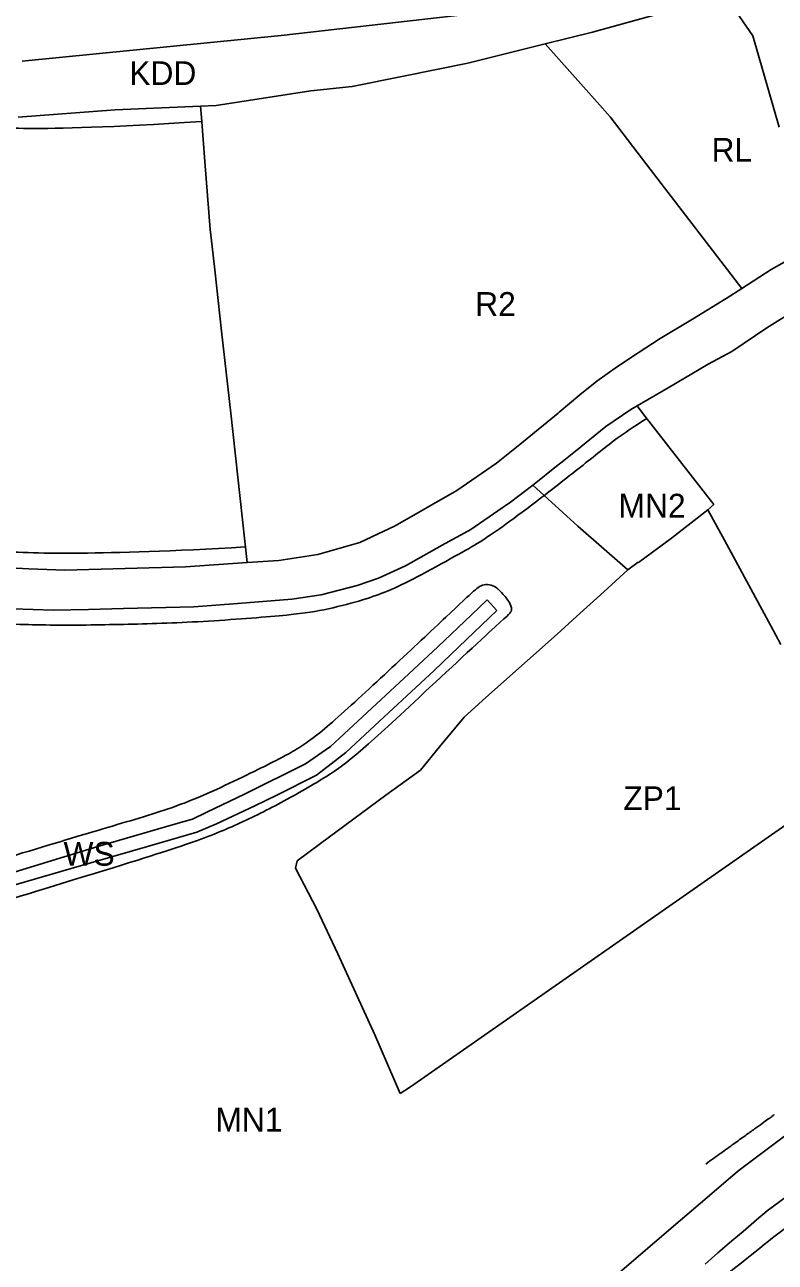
# Model space of a CAD drawing. Extents: x 7413438 to 7416393, y 5541665 to 5544118.
# Drawn here: x 7414642.6 to 7414832.1, y 5542969.5 to 5543282 of the extents above; entities that cross this region are included whole.
import ezdxf

# ---------------------------------------------------------------- set-up
doc = ezdxf.new("R2010")
doc.units = 0
for name, color, linetype in [('linie_rozgraniczajace', 7, 'Continuous'), ('linie_zabudowy_nieprzekraczalne', 7, 'Continuous'), ('oznaczenia_przeznaczen', 7, 'Continuous')]:
    doc.layers.add(name, color=color, linetype=linetype)

msp = doc.modelspace()

# ---------------------------------------------------------------- linework, layer by layer
at = {"layer": 'linie_rozgraniczajace'}
for p, q in [((7414785.95, 5543280.15), (7414819.64, 5543289.46)), ((7414765.82, 5543285.93), (7414707.33, 5543279.31)), ((7414826.4, 5543279.18), (7414820.45, 5543287.85)), ((7414774.02, 5543277.18), (7414785.95, 5543280.15)), ((7414707.33, 5543279.31), (7414641.96, 5543272.83)), ((7414754.51, 5543272.33), (7414774.02, 5543277.18)), ((7414774.02, 5543277.18), (7414787.16, 5543262.42)), ((7414833.08, 5543256.17), (7414826.4, 5543279.18)), ((7414738.24, 5543269.03), (7414754.51, 5543272.33)), ((7414725.25, 5543266.39), (7414738.24, 5543269.03)), ((7414690.96, 5543261.63), (7414714.83, 5543265.29)), ((7414714.83, 5543265.29), (7414725.25, 5543266.39)), ((7414665.43, 5543260.51), (7414686.96, 5543261.45)), ((7414686.96, 5543261.45), (7414690.96, 5543261.63)), ((7414686.96, 5543261.45), (7414687.19, 5543258.54)), ((7414787.16, 5543262.42), (7414790.41, 5543258.78)), ((7414640.94, 5543258.66), (7414665.43, 5543260.51)), ((7414687.19, 5543258.54), (7414688.08, 5543247.46)), ((7414790.41, 5543258.78), (7414800.54, 5543245.56)), ((7414688.08, 5543247.46), (7414689.46, 5543230.34)), ((7414800.54, 5543245.56), (7414823.62, 5543215.43)), ((7414689.46, 5543230.34), (7414689.94, 5543226.05)), ((7414689.94, 5543226.05), (7414690.6, 5543220.16)), ((7414831.03, 5543220.18), (7414837.77, 5543224.01)), ((7414690.6, 5543220.16), (7414692.29, 5543204.62)), ((7414823.62, 5543215.43), (7414831.03, 5543220.18)), ((7414819.69, 5543212.89), (7414823.62, 5543215.43)), ((7414811.22, 5543207.68), (7414819.69, 5543212.89)), ((7414803.07, 5543202.81), (7414811.22, 5543207.68)), ((7414829.99, 5543205.49), (7414838, 5543210.55)), ((7414692.29, 5543204.62), (7414694.63, 5543183.95)), ((7414821.13, 5543199.5), (7414829.99, 5543205.49)), ((7414797.5, 5543199.17), (7414803.07, 5543202.81)), ((7414792.25, 5543195.73), (7414797.5, 5543199.17)), ((7414815.11, 5543196.3), (7414821.13, 5543199.5)), ((7414787.07, 5543192.04), (7414792.25, 5543195.73)), ((7414805.07, 5543190.34), (7414815.11, 5543196.3)), ((7414782.74, 5543188.58), (7414787.07, 5543192.04)), ((7414797.21, 5543185.78), (7414805.07, 5543190.34)), ((7414777.52, 5543184.14), (7414782.74, 5543188.58)), ((7414795.59, 5543184.85), (7414797.21, 5543185.78)), ((7414797.21, 5543185.78), (7414798.67, 5543183.87)), ((7414694.63, 5543183.95), (7414698.76, 5543146.21)), ((7414767.58, 5543175.98), (7414777.26, 5543183.94)), ((7414777.26, 5543183.94), (7414777.52, 5543184.14)), ((7414789.32, 5543180.6), (7414795.59, 5543184.85)), ((7414798.67, 5543183.87), (7414798.72, 5543183.86)), ((7414798.72, 5543183.86), (7414798.69, 5543183.84)), ((7414798.69, 5543183.84), (7414816.59, 5543160.87)), ((7414781.66, 5543174.36), (7414789.32, 5543180.6)), ((7414761.68, 5543171.27), (7414767.58, 5543175.98)), ((7414779.09, 5543172.32), (7414781.66, 5543174.36)), ((7414751.68, 5543164.42), (7414761.68, 5543171.27)), ((7414771.19, 5543166.02), (7414776.85, 5543170.54)), ((7414776.85, 5543170.54), (7414777.94, 5543171.41)), ((7414777.94, 5543171.41), (7414779.09, 5543172.32)), ((7414736.12, 5543155.52), (7414751.68, 5543164.42)), ((7414765.23, 5543161.48), (7414770.89, 5543165.79)), ((7414770.89, 5543165.79), (7414771.19, 5543166.02)), ((7414782.27, 5543155.39), (7414770.89, 5543165.79)), ((7414763.89, 5543160.56), (7414765.23, 5543161.48)), ((7414816.59, 5543160.87), (7414815.1, 5543159.53)), ((7414755.22, 5543154.56), (7414763.17, 5543160.06)), ((7414763.17, 5543160.06), (7414763.89, 5543160.56)), ((7414815.1, 5543159.53), (7414805.87, 5543152.38)), ((7414815.1, 5543159.53), (7414819.25, 5543151.86)), ((7414730.26, 5543152.74), (7414736.12, 5543155.52)), ((7414747.98, 5543150.57), (7414755.22, 5543154.56)), ((7414794.9, 5543144.34), (7414782.27, 5543155.39)), ((7414727.18, 5543151.28), (7414730.26, 5543152.74)), ((7414805.87, 5543152.38), (7414797.54, 5543146.25)), ((7414819.25, 5543151.86), (7414830.96, 5543130.25)), ((7414706.73, 5543146.75), (7414716.63, 5543148.28)), ((7414716.63, 5543148.28), (7414727.18, 5543151.28)), ((7414738.72, 5543145.38), (7414747.98, 5543150.57)), ((7414643.66, 5543144.59), (7414633.27, 5543145.15)), ((7414683.2, 5543145.15), (7414652.69, 5543144.3)), ((7414698.76, 5543146.21), (7414683.2, 5543145.15)), ((7414698.76, 5543146.21), (7414706.73, 5543146.75)), ((7414731.88, 5543142.29), (7414738.72, 5543145.38)), ((7414797.49, 5543146.3), (7414794.9, 5543144.34)), ((7414797.54, 5543146.25), (7414797.49, 5543146.3)), ((7414652.69, 5543144.3), (7414643.66, 5543144.59)), ((7414726.55, 5543140.45), (7414731.88, 5543142.29)), ((7414788.82, 5543138.82), (7414794.9, 5543144.34)), ((7414717.47, 5543138.08), (7414726.55, 5543140.45)), ((7414685.32, 5543135.07), (7414696.39, 5543135.89)), ((7414696.39, 5543135.89), (7414710.04, 5543136.96)), ((7414710.04, 5543136.96), (7414717.47, 5543138.08)), ((7414755.44, 5543133.01), (7414759.36, 5543136.8)), ((7414759.36, 5543136.8), (7414761.8, 5543134.12)), ((7414781.88, 5543132.58), (7414788.82, 5543138.82)), ((7414639.6, 5543134.55), (7414649.9, 5543134.23)), ((7414649.9, 5543134.23), (7414658.7, 5543134.36)), ((7414658.7, 5543134.36), (7414667.5, 5543134.57)), ((7414667.5, 5543134.57), (7414685.32, 5543135.07)), ((7414746.91, 5543124.94), (7414755.44, 5543133.01)), ((7414761.8, 5543134.12), (7414752.22, 5543124.92)), ((7414776.99, 5543128.17), (7414781.88, 5543132.58)), ((7414830.96, 5543130.25), (7414833.49, 5543125.55)), ((7414769.54, 5543121.5), (7414777, 5543128.09)), ((7414777, 5543128.09), (7414776.99, 5543128.17)), ((7414739.6, 5543118.14), (7414746.91, 5543124.94)), ((7414752.22, 5543124.92), (7414746.01, 5543118.97)), ((7414759.03, 5543112.11), (7414769.54, 5543121.5)), ((7414726.7, 5543106.19), (7414739.6, 5543118.14)), ((7414746.01, 5543118.97), (7414732.15, 5543106.14)), ((7414753.51, 5543107.17), (7414759.03, 5543112.11)), ((7414719.83, 5543099.81), (7414726.7, 5543106.19)), ((7414732.15, 5543106.14), (7414723.63, 5543098.26)), ((7414747.35, 5543099.71), (7414753.51, 5543107.17)), ((7414713.51, 5543095.38), (7414719.83, 5543099.81)), ((7414723.63, 5543098.26), (7414716.23, 5543092.49)), ((7414742.49, 5543093.82), (7414747.35, 5543099.71)), ((7414698.05, 5543087.76), (7414713.51, 5543095.38)), ((7414716.23, 5543092.49), (7414706.22, 5543087.45)), ((7414733.79, 5543087.49), (7414742.49, 5543093.82)), ((7414851.64, 5543091.8), (7414740, 5543013.87)), ((7414688.59, 5543083.21), (7414698.05, 5543087.76)), ((7414706.22, 5543087.45), (7414700.69, 5543084.78)), ((7414719.53, 5543076.93), (7414733.79, 5543087.49)), ((7414684.95, 5543081.41), (7414688.59, 5543083.21)), ((7414700.69, 5543084.78), (7414691.06, 5543080.27)), ((7414661.06, 5543074.48), (7414680.77, 5543080.26)), ((7414680.77, 5543080.26), (7414684.95, 5543081.41)), ((7414691.06, 5543080.27), (7414686.06, 5543078.12)), ((7414686.06, 5543078.12), (7414674.19, 5543074.66)), ((7414711.36, 5543070.88), (7414719.53, 5543076.93)), ((7414630.15, 5543065.09), (7414661.06, 5543074.48)), ((7414674.19, 5543074.66), (7414654.32, 5543068.97)), ((7414710.97, 5543069.02), (7414711.36, 5543070.88)), ((7414654.32, 5543068.97), (7414637.83, 5543064.13)), ((7414716.36, 5543058.72), (7414710.97, 5543069.02)), ((7414721.66, 5543047.45), (7414716.36, 5543058.72)), ((7414731.02, 5543026.97), (7414721.66, 5543047.45)), ((7414737.35, 5543012.16), (7414731.02, 5543026.97)), ((7414740, 5543013.87), (7414737.35, 5543012.16)), ((7414837.45, 5543003.66), (7414827.02, 5542995.87)), ((7414827.02, 5542995.87), (7414822.96, 5542992.84)), ((7414822.96, 5542992.84), (7414820.9, 5542991.07)), ((7414820.9, 5542991.07), (7414815.47, 5542986.43)), ((7414815.47, 5542986.43), (7414808.04, 5542980.06)), ((7414830.03, 5542982.53), (7414835.16, 5542986.36)), ((7414808.04, 5542980.06), (7414795.77, 5542969.55)), ((7414823.98, 5542977.34), (7414827.38, 5542980.26)), ((7414827.38, 5542980.26), (7414830.03, 5542982.53)), ((7414821.16, 5542974.92), (7414823.98, 5542977.34)), ((7414817.63, 5542971.89), (7414821.16, 5542974.92)), ((7414814.37, 5542969.1), (7414817.63, 5542971.89)), ((7414795.77, 5542969.55), (7414785.4, 5542960.67))]:
    msp.add_line(p, q, dxfattribs=at)
at = {"layer": 'linie_zabudowy_nieprzekraczalne'}
for points, degree in [([(7414687.23, 5543257.54), (7414640.54, 5543254.67), (7414631.57, 5543257.54), (7414619.22, 5543256.49), (7414614.66, 5543262.9), (7414609.18, 5543264.16), (7414546.97, 5543257.6), (7414481.96, 5543252.26), (7414449.78, 5543249.6), (7414442.77, 5543244.55), (7414429.85, 5543242.9)], 3), ([(7414799.65, 5543182.56), (7414796.22, 5543180.46), (7414791.68, 5543177.37), (7414781.93, 5543169.49), (7414769.91, 5543160.14), (7414761.92, 5543154.35), (7414757.12, 5543151.05), (7414750.78, 5543147.55), (7414739.82, 5543141.5), (7414733.49, 5543138.64), (7414727.52, 5543136.56), (7414718.03, 5543134.11), (7414709.3, 5543132.88), (7414685.58, 5543131.07), (7414666.16, 5543130.53), (7414647.72, 5543130.28), (7414630.48, 5543131.05), (7414620.36, 5543131.68), (7414616.12, 5543131.26), (7414612.81, 5543129.71), (7414609.64, 5543127.09), (7414608.29, 5543125.86), (7414608.06, 5543122.81)], 3), ([(7414341.07, 5543163.28), (7414356.51, 5543147.6), (7414375.53, 5543125.83), (7414392.4, 5543108.91), (7414398.25, 5543103.17), (7414401.25, 5543100.02), (7414408.23, 5543099.78), (7414415, 5543102.86), (7414429.11, 5543104.87), (7414443.72, 5543106.55), (7414466.68, 5543108.58), (7414484.3, 5543105.95), (7414507.74, 5543103.66), (7414536.5, 5543101.14), (7414544.43, 5543101.85), (7414560.45, 5543105.29), (7414569.76, 5543106.57), (7414580.19, 5543106.45), (7414585, 5543107.07), (7414589.21, 5543110.97), (7414589.59, 5543117.25), (7414589.25, 5543126.63), (7414589.81, 5543129.39), (7414593.09, 5543140.49), (7414594.13, 5543144.01), (7414594.78, 5543145.14), (7414596.31, 5543146.56), (7414597.95, 5543147.56), (7414603.22, 5543149.61), (7414607.81, 5543150.14), (7414636.45, 5543148.97), (7414652.66, 5543148.29), (7414679.53, 5543149.04), (7414698.29, 5543150.16)], 3), ([(7414431.95, 5543087.28), (7414424.23, 5543086.19), (7414420.06, 5543085.34), (7414419, 5543080.42), (7414421.28, 5543073.71), (7414423.39, 5543062.01), (7414425.39, 5543058.29), (7414430.81, 5543048.92), (7414433.87, 5543045.88), (7414444.69, 5543042.35), (7414474.63, 5543035.39), (7414481.89, 5543033.43), (7414483.16, 5543036.96), (7414485.08, 5543039.86), (7414490.96, 5543045.85), (7414497.7, 5543051.64), (7414500.63, 5543053.95), (7414503, 5543055.91), (7414505.09, 5543056.77), (7414509.77, 5543055.9), (7414530.22, 5543051.06), (7414537.37, 5543048.9), (7414539.27, 5543048.01), (7414540.33, 5543046.71), (7414543.6, 5543045.77), (7414547.8, 5543044.76), (7414549.47, 5543044.91), (7414562.64, 5543048.9), (7414579.93, 5543054.1), (7414600, 5543060.19), (7414616.25, 5543065.09), (7414646.94, 5543074.37), (7414667.99, 5543080.68), (7414683.48, 5543085.15), (7414703.27, 5543094.8), (7414711.92, 5543099.17), (7414719.64, 5543105.12), (7414735.49, 5543119.82), (7414750.36, 5543133.73), (7414756.76, 5543139.86), (7414758.13, 5543140.61), (7414759.94, 5543140.74), (7414761.63, 5543140.06), (7414763.36, 5543138.3), (7414765.4, 5543135.79), (7414765.75, 5543133.75), (7414763.94, 5543132.46), (7414737.28, 5543107.58), (7414725.35, 5543096.6), (7414718.45, 5543091.83), (7414705.59, 5543084.52), (7414694.22, 5543079.04), (7414682.4, 5543074.49), (7414654.76, 5543066.06), (7414598.61, 5543048.77), (7414574.71, 5543041.85)], 3), ([(7414814.55, 5542994.35), (7414831.17, 5543006.32), (7414831.84, 5543006.8)], 2), ([(7414865.41, 5543001.51), (7414863.31, 5542999.93), (7414863.3, 5542999.93), (7414841.57, 5542983.67), (7414834.34, 5542978.05), (7414809.62, 5542958.24), (7414800.27, 5542951.67), (7414797.78, 5542948.59)], 3)]:
    msp.add_open_spline(points, degree=degree, dxfattribs=at)

# ---------------------------------------------------------------- texts
at = {"layer": 'oznaczenia_przeznaczen'}
for s, p in [('KDD', (7414669, 5543266.79)), ('RL', (7414816.01, 5543247.42)), ('R2', (7414756.34, 5543208.49)), ('MN2', (7414792.52, 5543157.57)), ('ZP1', (7414793.72, 5543083.71)), ('WS', (7414652.39, 5543069.68)), ('MN1', (7414690.73, 5543002.56))]:
    msp.add_text(s, height=6, dxfattribs=at).set_placement(p)

doc.saveas('drawing.dxf')
